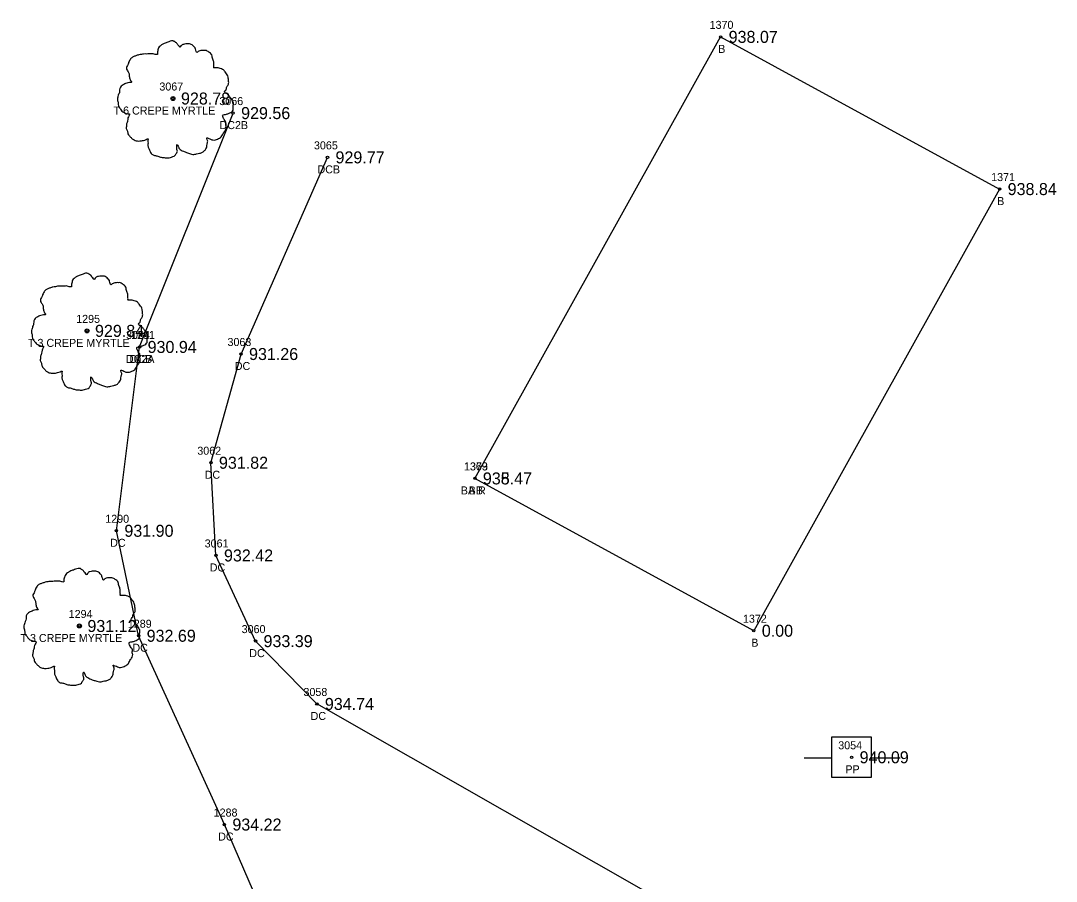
# Model space of a CAD drawing. Extents: x 1528109 to 1531398, y 1157799 to 1162548.
# Drawn here: x 1529934.5 to 1530063.8, y 1159536.7 to 1159644.1 of the extents above; entities that cross this region are included whole.
import ezdxf

# ---------------------------------------------------------------- set-up
doc = ezdxf.new("R2010")
doc.units = 0
for name, color, linetype in [('RD_EX_Bldg', 7, 'Continuous'), ('RD_EX_Bldg_txCode', 7, 'Continuous'), ('RD_EX_Conc', 7, 'Continuous'), ('RD_EX_Conc_txCode', 7, 'Continuous'), ('RD_EX_TX_Bldg_ELEV', 7, 'Continuous'), ('RD_EX_TX_Conc_ELEV', 7, 'Continuous'), ('RD_EX_TX_VEG_ELEV', 7, 'Continuous'), ('RD_EX_UT', 7, 'Continuous'), ('RD_EX_UT_txCode', 7, 'Continuous'), ('RD_EX_VEG', 7, 'Continuous'), ('RD_EX_VEG_txCode', 7, 'Continuous'), ('RD_HC_Survey_ELEV', 7, 'Continuous'), ('RD_SMD_Locator', 7, 'Continuous')]:
    doc.layers.add(name, color=color, linetype=linetype)

msp = doc.modelspace()

# ---------------------------------------------------------------- linework, layer by layer
at = {"layer": 'RD_EX_Bldg'}
msp.add_lwpolyline([(1529991.2, 1159586.98), (1530021.9, 1159642.13), (1530056.75, 1159623.12), (1530026.04, 1159567.96), (1529991.2, 1159586.98)], dxfattribs=at)
at = {"layer": 'RD_EX_Conc'}
msp.add_line((1529949.32, 1159603.4), (1529961, 1159632.61), dxfattribs=at)
for points in [[(1529985.36, 1159513.53), (1530001.66, 1159503.51), (1530018.15, 1159532.17), (1529971.46, 1159558.81), (1529963.8, 1159566.66), (1529958.86, 1159577.36), (1529958.23, 1159588.94), (1529961.99, 1159602.52), (1529972.79, 1159627.08)], [(1529985.36, 1159513.53), (1529971.94, 1159498.7), (1529967.31, 1159509.07), (1529968.13, 1159521.49), (1529967.72, 1159525.76), (1529959.91, 1159543.75), (1529949.2, 1159567.33), (1529946.42, 1159580.44), (1529949.32, 1159603.4)]]:
    msp.add_lwpolyline(points, dxfattribs=at)
at = {"layer": 'RD_EX_UT'}
for p, q in [((1530040.75, 1159554.66), (1530035.75, 1159554.66)), ((1530035.75, 1159554.66), (1530035.75, 1159549.66)), ((1530040.75, 1159549.66), (1530040.75, 1159554.66)), ((1530032.32, 1159552.09), (1530035.79, 1159552.09)), ((1530040.68, 1159552.09), (1530044.32, 1159552.09)), ((1530035.75, 1159549.66), (1530040.75, 1159549.66))]:
    msp.add_line(p, q, dxfattribs=at)
at = {"layer": 'RD_EX_VEG'}
for centre, radius in [((1529953.49, 1159634.43), 0.25), ((1529953.47, 1159634.41), 0.0001), ((1529942.75, 1159605.41), 0.25), ((1529942.74, 1159605.39), 0.0001), ((1529941.8, 1159568.55), 0.25), ((1529941.79, 1159568.53), 0.0001)]:
    msp.add_circle(centre, radius, dxfattribs=at)
for points in [[(1529953.62, 1159641.59), (1529953.32, 1159641.62), (1529952.99, 1159641.52), (1529952.74, 1159641.42), (1529952.52, 1159641.34), (1529952.29, 1159641.24), (1529951.99, 1159641.07), (1529951.77, 1159640.87), (1529951.64, 1159640.62), (1529951.59, 1159640.39), (1529951.54, 1159640.12), (1529951.54, 1159639.94), (1529951.42, 1159639.92), (1529951.27, 1159639.94), (1529951.02, 1159640.02), (1529950.77, 1159640.02), (1529950.52, 1159640.02), (1529950.17, 1159639.99), (1529949.82, 1159639.99), (1529949.55, 1159639.94), (1529949.22, 1159639.89), (1529948.85, 1159639.77), (1529948.5, 1159639.64), (1529948.2, 1159639.39), (1529947.95, 1159638.92), (1529947.82, 1159638.57), (1529947.67, 1159638.32), (1529947.82, 1159637.87), (1529948, 1159637.52), (1529948.02, 1159637.32), (1529948.1, 1159636.9), (1529948.2, 1159636.67), (1529948.32, 1159636.47), (1529948.25, 1159636.45), (1529947.87, 1159636.4), (1529947.57, 1159636.3), (1529947.15, 1159636.07), (1529946.92, 1159635.85), (1529946.82, 1159635.52), (1529946.8, 1159635.17), (1529946.7, 1159634.97), (1529946.62, 1159634.7), (1529946.6, 1159634.62), (1529946.55, 1159634.3), (1529946.65, 1159633.85), (1529946.67, 1159633.5), (1529946.8, 1159633.27), (1529946.95, 1159633.1), (1529947.12, 1159632.85), (1529947.52, 1159632.62), (1529947.85, 1159632.52), (1529948.05, 1159632.5), (1529947.87, 1159632), (1529947.82, 1159631.65), (1529947.7, 1159631.25), (1529947.7, 1159631.17), (1529947.65, 1159630.7), (1529947.8, 1159630.37), (1529947.87, 1159630), (1529948.05, 1159629.77), (1529948.32, 1159629.47), (1529948.65, 1159629.25), (1529949.15, 1159629.12), (1529949.55, 1159629.15), (1529950.12, 1159629.32), (1529950.37, 1159629.4), (1529950.35, 1159629.22), (1529950.37, 1159628.85), (1529950.37, 1159628.42), (1529950.52, 1159628.1), (1529950.62, 1159627.82), (1529950.77, 1159627.57), (1529951.09, 1159627.35), (1529951.49, 1159627.27), (1529951.92, 1159627.12), (1529952.37, 1159627.05), (1529952.87, 1159627.02), (1529953.47, 1159627.17), (1529953.74, 1159627.3), (1529953.84, 1159627.47), (1529954.04, 1159627.85), (1529953.99, 1159628.07), (1529954.02, 1159628.67), (1529954.12, 1159628.5), (1529954.29, 1159628.15), (1529954.79, 1159627.85), (1529955.19, 1159627.67), (1529955.67, 1159627.52), (1529955.97, 1159627.45), (1529956.44, 1159627.52), (1529956.82, 1159627.6), (1529957.19, 1159627.72), (1529957.49, 1159628), (1529957.67, 1159628.27), (1529957.72, 1159628.55), (1529957.79, 1159628.92), (1529957.84, 1159629.1)], [(1529957.84, 1159629.1), (1529957.77, 1159629.27), (1529957.72, 1159629.52), (1529957.79, 1159629.5), (1529957.97, 1159629.45), (1529958.24, 1159629.32), (1529958.47, 1159629.25), (1529958.79, 1159629.27), (1529959.07, 1159629.37), (1529959.52, 1159629.65), (1529959.79, 1159630.12), (1529960.07, 1159630.52), (1529960.14, 1159630.85), (1529960.09, 1159631.07), (1529960.07, 1159631.57), (1529959.87, 1159631.82), (1529959.82, 1159631.95), (1529959.72, 1159632.35), (1529959.79, 1159632.4), (1529960.07, 1159632.45), (1529960.44, 1159632.57), (1529960.72, 1159632.7), (1529960.94, 1159632.87), (1529961.02, 1159633.1), (1529960.99, 1159633.5), (1529961.04, 1159633.9), (1529960.97, 1159634.05), (1529960.87, 1159634.2), (1529960.79, 1159634.4), (1529960.64, 1159634.55), (1529960.54, 1159634.7), (1529960.44, 1159634.8), (1529960.32, 1159634.95), (1529960.14, 1159635.07), (1529959.99, 1159635.12), (1529959.94, 1159635.27), (1529960.09, 1159635.47), (1529960.14, 1159635.57), (1529960.17, 1159635.8), (1529960.39, 1159636.15), (1529960.44, 1159636.55), (1529960.39, 1159636.97), (1529960.34, 1159637.25), (1529960.19, 1159637.52), (1529959.99, 1159637.77), (1529959.87, 1159637.95), (1529959.69, 1159638.07), (1529959.37, 1159638.2), (1529959.12, 1159638.25), (1529958.77, 1159638.25), (1529958.57, 1159638.3), (1529958.59, 1159638.35), (1529958.59, 1159638.49), (1529958.59, 1159638.77), (1529958.52, 1159639.22), (1529958.37, 1159639.72), (1529958.37, 1159639.74), (1529958.27, 1159639.99), (1529958.04, 1159640.19), (1529957.87, 1159640.29), (1529957.67, 1159640.42), (1529957.42, 1159640.44), (1529957.12, 1159640.44), (1529956.84, 1159640.39), (1529956.64, 1159640.29), (1529956.47, 1159640.17), (1529956.39, 1159640.32), (1529956.29, 1159640.62), (1529956.24, 1159640.77), (1529956.09, 1159640.94), (1529955.87, 1159641.14), (1529955.42, 1159641.27), (1529954.79, 1159641.19), (1529954.49, 1159640.99), (1529954.34, 1159640.82), (1529954.29, 1159640.94), (1529954.09, 1159641.14), (1529953.99, 1159641.32), (1529953.82, 1159641.44), (1529953.67, 1159641.54), (1529953.57, 1159641.59)], [(1529942.88, 1159612.58), (1529942.58, 1159612.61), (1529942.26, 1159612.51), (1529942.01, 1159612.41), (1529941.78, 1159612.33), (1529941.56, 1159612.23), (1529941.26, 1159612.06), (1529941.03, 1159611.86), (1529940.91, 1159611.61), (1529940.86, 1159611.38), (1529940.81, 1159611.11), (1529940.81, 1159610.93), (1529940.68, 1159610.91), (1529940.53, 1159610.93), (1529940.28, 1159611.01), (1529940.03, 1159611.01), (1529939.78, 1159611.01), (1529939.43, 1159610.98), (1529939.08, 1159610.98), (1529938.81, 1159610.93), (1529938.48, 1159610.88), (1529938.11, 1159610.76), (1529937.76, 1159610.63), (1529937.46, 1159610.38), (1529937.21, 1159609.91), (1529937.08, 1159609.56), (1529936.93, 1159609.31), (1529937.08, 1159608.86), (1529937.26, 1159608.51), (1529937.28, 1159608.31), (1529937.36, 1159607.88), (1529937.46, 1159607.66), (1529937.58, 1159607.46), (1529937.51, 1159607.43), (1529937.13, 1159607.38), (1529936.83, 1159607.28), (1529936.41, 1159607.06), (1529936.19, 1159606.83), (1529936.09, 1159606.51), (1529936.06, 1159606.16), (1529935.96, 1159605.96), (1529935.89, 1159605.68), (1529935.86, 1159605.61), (1529935.81, 1159605.28), (1529935.91, 1159604.83), (1529935.94, 1159604.48), (1529936.06, 1159604.26), (1529936.21, 1159604.08), (1529936.39, 1159603.83), (1529936.78, 1159603.61), (1529937.11, 1159603.51), (1529937.31, 1159603.48), (1529937.13, 1159602.99), (1529937.08, 1159602.64), (1529936.96, 1159602.24), (1529936.96, 1159602.16), (1529936.91, 1159601.69), (1529937.06, 1159601.36), (1529937.13, 1159600.99), (1529937.31, 1159600.76), (1529937.58, 1159600.46), (1529937.91, 1159600.24), (1529938.41, 1159600.11), (1529938.81, 1159600.14), (1529939.38, 1159600.31), (1529939.63, 1159600.39), (1529939.61, 1159600.21), (1529939.63, 1159599.84), (1529939.63, 1159599.41), (1529939.78, 1159599.09), (1529939.88, 1159598.81), (1529940.03, 1159598.56), (1529940.36, 1159598.34), (1529940.76, 1159598.26), (1529941.18, 1159598.11), (1529941.63, 1159598.04), (1529942.13, 1159598.01), (1529942.73, 1159598.16), (1529943.01, 1159598.29), (1529943.11, 1159598.46), (1529943.31, 1159598.84), (1529943.26, 1159599.06), (1529943.28, 1159599.66), (1529943.38, 1159599.49), (1529943.56, 1159599.14), (1529944.06, 1159598.84), (1529944.46, 1159598.66), (1529944.93, 1159598.51), (1529945.23, 1159598.44), (1529945.71, 1159598.51), (1529946.08, 1159598.59), (1529946.46, 1159598.71), (1529946.76, 1159598.99), (1529946.93, 1159599.26), (1529946.98, 1159599.54), (1529947.06, 1159599.91), (1529947.11, 1159600.09)], [(1529947.11, 1159600.09), (1529947.03, 1159600.26), (1529946.98, 1159600.51), (1529947.06, 1159600.49), (1529947.23, 1159600.44), (1529947.51, 1159600.31), (1529947.73, 1159600.24), (1529948.05, 1159600.26), (1529948.33, 1159600.36), (1529948.78, 1159600.64), (1529949.05, 1159601.11), (1529949.33, 1159601.51), (1529949.4, 1159601.84), (1529949.35, 1159602.06), (1529949.33, 1159602.56), (1529949.13, 1159602.81), (1529949.08, 1159602.94), (1529948.98, 1159603.33), (1529949.05, 1159603.38), (1529949.33, 1159603.43), (1529949.7, 1159603.56), (1529949.98, 1159603.68), (1529950.2, 1159603.86), (1529950.28, 1159604.08), (1529950.25, 1159604.48), (1529950.3, 1159604.88), (1529950.23, 1159605.03), (1529950.13, 1159605.18), (1529950.05, 1159605.38), (1529949.9, 1159605.53), (1529949.8, 1159605.68), (1529949.7, 1159605.78), (1529949.58, 1159605.93), (1529949.4, 1159606.06), (1529949.25, 1159606.11), (1529949.2, 1159606.26), (1529949.35, 1159606.46), (1529949.4, 1159606.56), (1529949.43, 1159606.78), (1529949.65, 1159607.13), (1529949.7, 1159607.53), (1529949.65, 1159607.96), (1529949.6, 1159608.23), (1529949.45, 1159608.51), (1529949.25, 1159608.76), (1529949.13, 1159608.93), (1529948.95, 1159609.06), (1529948.63, 1159609.18), (1529948.38, 1159609.23), (1529948.03, 1159609.23), (1529947.83, 1159609.28), (1529947.86, 1159609.33), (1529947.86, 1159609.48), (1529947.86, 1159609.76), (1529947.78, 1159610.21), (1529947.63, 1159610.71), (1529947.63, 1159610.73), (1529947.53, 1159610.98), (1529947.31, 1159611.18), (1529947.13, 1159611.28), (1529946.93, 1159611.41), (1529946.68, 1159611.43), (1529946.38, 1159611.43), (1529946.11, 1159611.38), (1529945.91, 1159611.28), (1529945.73, 1159611.16), (1529945.66, 1159611.31), (1529945.56, 1159611.61), (1529945.51, 1159611.76), (1529945.36, 1159611.93), (1529945.13, 1159612.13), (1529944.68, 1159612.26), (1529944.06, 1159612.18), (1529943.76, 1159611.98), (1529943.61, 1159611.81), (1529943.56, 1159611.93), (1529943.36, 1159612.13), (1529943.26, 1159612.31), (1529943.08, 1159612.43), (1529942.93, 1159612.53), (1529942.83, 1159612.58)], [(1529941.94, 1159575.72), (1529941.64, 1159575.74), (1529941.31, 1159575.64), (1529941.06, 1159575.54), (1529940.84, 1159575.47), (1529940.61, 1159575.37), (1529940.31, 1159575.19), (1529940.09, 1159574.99), (1529939.96, 1159574.74), (1529939.91, 1159574.52), (1529939.86, 1159574.24), (1529939.86, 1159574.07), (1529939.74, 1159574.04), (1529939.59, 1159574.07), (1529939.34, 1159574.14), (1529939.09, 1159574.14), (1529938.84, 1159574.14), (1529938.49, 1159574.12), (1529938.14, 1159574.12), (1529937.86, 1159574.07), (1529937.54, 1159574.02), (1529937.16, 1159573.89), (1529936.81, 1159573.77), (1529936.51, 1159573.52), (1529936.26, 1159573.04), (1529936.14, 1159572.69), (1529935.99, 1159572.44), (1529936.14, 1159571.99), (1529936.31, 1159571.64), (1529936.34, 1159571.44), (1529936.41, 1159571.02), (1529936.51, 1159570.79), (1529936.64, 1159570.59), (1529936.56, 1159570.57), (1529936.19, 1159570.52), (1529935.89, 1159570.42), (1529935.46, 1159570.19), (1529935.24, 1159569.97), (1529935.14, 1159569.64), (1529935.11, 1159569.29), (1529935.01, 1159569.09), (1529934.94, 1159568.82), (1529934.91, 1159568.74), (1529934.86, 1159568.42), (1529934.96, 1159567.97), (1529934.99, 1159567.62), (1529935.11, 1159567.4), (1529935.26, 1159567.22), (1529935.44, 1159566.97), (1529935.84, 1159566.75), (1529936.16, 1159566.65), (1529936.36, 1159566.62), (1529936.19, 1159566.12), (1529936.14, 1159565.77), (1529936.01, 1159565.37), (1529936.01, 1159565.3), (1529935.96, 1159564.82), (1529936.11, 1159564.5), (1529936.19, 1159564.12), (1529936.36, 1159563.9), (1529936.64, 1159563.6), (1529936.96, 1159563.37), (1529937.46, 1159563.25), (1529937.86, 1159563.27), (1529938.44, 1159563.45), (1529938.69, 1159563.52), (1529938.66, 1159563.35), (1529938.69, 1159562.97), (1529938.69, 1159562.55), (1529938.84, 1159562.22), (1529938.94, 1159561.95), (1529939.09, 1159561.7), (1529939.41, 1159561.47), (1529939.81, 1159561.4), (1529940.24, 1159561.25), (1529940.69, 1159561.17), (1529941.19, 1159561.15), (1529941.79, 1159561.3), (1529942.06, 1159561.42), (1529942.16, 1159561.6), (1529942.36, 1159561.97), (1529942.31, 1159562.2), (1529942.34, 1159562.8), (1529942.44, 1159562.62), (1529942.61, 1159562.27), (1529943.11, 1159561.97), (1529943.51, 1159561.8), (1529943.99, 1159561.65), (1529944.29, 1159561.57), (1529944.76, 1159561.65), (1529945.14, 1159561.72), (1529945.51, 1159561.85), (1529945.81, 1159562.12), (1529945.98, 1159562.4), (1529946.03, 1159562.67), (1529946.11, 1159563.05), (1529946.16, 1159563.22)], [(1529946.16, 1159563.22), (1529946.08, 1159563.4), (1529946.03, 1159563.65), (1529946.11, 1159563.62), (1529946.28, 1159563.57), (1529946.56, 1159563.45), (1529946.78, 1159563.37), (1529947.11, 1159563.4), (1529947.38, 1159563.5), (1529947.83, 1159563.77), (1529948.11, 1159564.25), (1529948.38, 1159564.65), (1529948.46, 1159564.97), (1529948.41, 1159565.2), (1529948.38, 1159565.7), (1529948.18, 1159565.95), (1529948.13, 1159566.07), (1529948.03, 1159566.47), (1529948.11, 1159566.52), (1529948.38, 1159566.57), (1529948.76, 1159566.7), (1529949.03, 1159566.82), (1529949.26, 1159567), (1529949.33, 1159567.22), (1529949.31, 1159567.62), (1529949.36, 1159568.02), (1529949.28, 1159568.17), (1529949.18, 1159568.32), (1529949.11, 1159568.52), (1529948.96, 1159568.67), (1529948.86, 1159568.82), (1529948.76, 1159568.92), (1529948.63, 1159569.07), (1529948.46, 1159569.19), (1529948.31, 1159569.24), (1529948.26, 1159569.39), (1529948.41, 1159569.59), (1529948.46, 1159569.69), (1529948.48, 1159569.92), (1529948.71, 1159570.27), (1529948.76, 1159570.67), (1529948.71, 1159571.09), (1529948.66, 1159571.37), (1529948.51, 1159571.64), (1529948.31, 1159571.89), (1529948.18, 1159572.07), (1529948.01, 1159572.19), (1529947.68, 1159572.32), (1529947.43, 1159572.37), (1529947.08, 1159572.37), (1529946.88, 1159572.42), (1529946.91, 1159572.47), (1529946.91, 1159572.62), (1529946.91, 1159572.89), (1529946.83, 1159573.34), (1529946.68, 1159573.84), (1529946.68, 1159573.87), (1529946.58, 1159574.12), (1529946.36, 1159574.32), (1529946.18, 1159574.42), (1529945.98, 1159574.54), (1529945.74, 1159574.57), (1529945.44, 1159574.57), (1529945.16, 1159574.52), (1529944.96, 1159574.42), (1529944.79, 1159574.29), (1529944.71, 1159574.44), (1529944.61, 1159574.74), (1529944.56, 1159574.89), (1529944.41, 1159575.07), (1529944.19, 1159575.27), (1529943.74, 1159575.39), (1529943.11, 1159575.32), (1529942.81, 1159575.12), (1529942.66, 1159574.94), (1529942.61, 1159575.07), (1529942.41, 1159575.27), (1529942.31, 1159575.44), (1529942.14, 1159575.57), (1529941.99, 1159575.67), (1529941.89, 1159575.72)]]:
    msp.add_spline(points, degree=3, dxfattribs=at)
at = {"layer": 'RD_SMD_Locator'}
for centre in [(1530021.9, 1159642.13), (1529953.49, 1159634.43), (1529961, 1159632.61), (1529972.79, 1159627.08), (1530056.75, 1159623.12), (1529942.75, 1159605.41), (1529949.32, 1159603.4), (1529949.32, 1159603.4), (1529961.99, 1159602.52), (1529958.23, 1159588.94), (1529991.2, 1159586.98), (1529991.2, 1159586.98), (1529946.42, 1159580.44), (1529958.86, 1159577.36), (1529941.8, 1159568.55), (1530026.04, 1159567.96), (1529949.2, 1159567.33), (1529963.8, 1159566.66), (1529971.46, 1159558.81), (1530038.26, 1159552.15), (1529959.91, 1159543.75)]:
    msp.add_circle(centre, 0.15, dxfattribs=at)

# ---------------------------------------------------------------- texts
at = {"layer": 'RD_EX_Bldg_txCode'}
for s, p in [('1370', (1530020.52, 1159643.13)), ('B', (1530021.6, 1159640.13)), ('1371', (1530055.69, 1159624.12)), ('B', (1530056.44, 1159621.12)), ('1369', (1529989.83, 1159587.98)), ('1373', (1529989.85, 1159587.98)), ('BA R', (1529989.44, 1159584.98)), ('BB', (1529990.42, 1159584.98)), ('1372', (1530024.69, 1159568.96)), ('B', (1530025.73, 1159565.96))]:
    msp.add_text(s, height=1, dxfattribs=at).set_placement(p)
at = {"layer": 'RD_EX_Conc_txCode'}
for s, p in [('3066', (1529959.28, 1159633.61)), ('DC2B', (1529959.3, 1159630.61)), ('3065', (1529971.1, 1159628.08)), ('DCB', (1529971.54, 1159625.08)), ('3064', (1529947.63, 1159604.4)), ('1291', (1529948.26, 1159604.4)), ('3063', (1529960.3, 1159603.52)), ('DC2A', (1529947.61, 1159601.4)), ('DCB', (1529948.07, 1159601.4)), ('DC', (1529961.21, 1159600.52)), ('3062', (1529956.53, 1159589.94)), ('DC', (1529957.45, 1159586.94)), ('1290', (1529945.03, 1159581.44)), ('DC', (1529945.64, 1159578.44)), ('3061', (1529957.45, 1159578.36)), ('DC', (1529958.08, 1159575.36)), ('1289', (1529947.85, 1159568.33)), ('3060', (1529962.07, 1159567.66)), ('DC', (1529948.42, 1159565.33)), ('DC', (1529963.02, 1159564.66)), ('3058', (1529969.79, 1159559.81)), ('DC', (1529970.68, 1159556.81)), ('1288', (1529958.57, 1159544.75)), ('DC', (1529959.13, 1159541.75))]:
    msp.add_text(s, height=1, dxfattribs=at).set_placement(p)
at = {"layer": 'RD_EX_TX_Bldg_ELEV'}
for s, p in [('938.07', (1530022.9, 1159641.38)), ('938.84', (1530057.75, 1159622.37)), ('938.47', (1529992.2, 1159586.23)), ('935.47', (1529992.2, 1159586.23)), ('0.00', (1530027.04, 1159567.21))]:
    msp.add_text(s, height=1.5, dxfattribs=at).set_placement(p)
at = {"layer": 'RD_EX_TX_Conc_ELEV'}
for s, p in [('929.56', (1529962, 1159631.86)), ('929.77', (1529973.79, 1159626.33)), ('930.94', (1529950.32, 1159602.65)), ('930.94', (1529950.32, 1159602.65)), ('931.26', (1529962.99, 1159601.77)), ('931.82', (1529959.23, 1159588.19)), ('931.90', (1529947.42, 1159579.69)), ('932.42', (1529959.86, 1159576.61)), ('932.69', (1529950.2, 1159566.58)), ('933.39', (1529964.8, 1159565.91)), ('934.74', (1529972.46, 1159558.06)), ('934.22', (1529960.91, 1159543))]:
    msp.add_text(s, height=1.5, dxfattribs=at).set_placement(p)
at = {"layer": 'RD_EX_TX_VEG_ELEV'}
for s, p in [('928.78', (1529954.49, 1159633.68)), ('929.84', (1529943.75, 1159604.66)), ('931.12', (1529942.8, 1159567.8))]:
    msp.add_text(s, height=1.5, dxfattribs=at).set_placement(p)
at = {"layer": 'RD_EX_UT_txCode'}
for s, p in [('3054', (1530036.59, 1159553.15)), ('PP', (1530037.48, 1159550.15))]:
    msp.add_text(s, height=1, dxfattribs=at).set_placement(p)
at = {"layer": 'RD_EX_VEG_txCode'}
for s, p in [('3067', (1529951.79, 1159635.43)), ('T 6 CREPE MYRTLE', (1529946.07, 1159632.43)), ('1295', (1529941.4, 1159606.41)), ('T 3 CREPE MYRTLE', (1529935.38, 1159603.41)), ('1294', (1529940.46, 1159569.55)), ('T 3 CREPE MYRTLE', (1529934.44, 1159566.55))]:
    msp.add_text(s, height=1, dxfattribs=at).set_placement(p)
at = {"layer": 'RD_HC_Survey_ELEV'}
msp.add_text('940.09', height=1.5, dxfattribs=at).set_placement((1530039.26, 1159551.4))

doc.saveas('drawing.dxf')
